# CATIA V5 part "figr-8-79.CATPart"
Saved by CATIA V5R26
Part number: Part1
Bounding box of the stored display mesh (mm): x -35 to 35, y -116.369 to 116.369, z 0 to 117.647
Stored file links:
  D:\_Deepak\CATIA\CATIA V5-6R2016_Deepak\Resources\Part files\Partfiles\c08_catia_v5_6r2016_prt\figr-8-79.CATPart
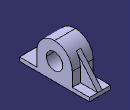
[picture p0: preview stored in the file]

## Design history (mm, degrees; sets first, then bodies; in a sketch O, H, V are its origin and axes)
Body1 (main body)
  Sketch1 on yz-plane, origin (0, 0, 0), H (0, 1, 0), V (0, 0, 1)
    line L1 (0, 0) -> (116.3687, 0)
    point P1 (116.3687, 0)
    line L2 (116.3687, 0) -> (116.3687, 12.5279)
    point P2 (116.3687, 12.5279)
    line L3 (116.3687, 12.5279) -> (58.943, 12.5279)
    point P3 (58.943, 12.5279)
    line L4 (58.943, 12.5279) -> (58.943, 58.7038)
    point P4 (58.943, 58.7038)
    arc A1 centre (0, 58.7038) radius 58.943 from (58.943, 58.7038) to (0, 117.6467) ccw
    point P5 (0, 58.7038)
    point P6 (-58.943, 58.7038)
    line L5 (-58.943, 58.7038) -> (-58.943, 12.5279)
    point P7 (-58.943, 12.5279)
    axis line L6 (0, 0) -> (0, 108.1111)
    point P9 (0, 117.6467)
    point P10 (0, 117.6467)
    point P11 (-58.943, 58.7038)
    arc A2 centre (0, 58.7038) radius 58.943 from (-58.943, 58.7038) to (0, 117.6467) cw
    point P13 (-58.943, 12.5279)
    point P14 (-116.3687, 12.5279)
    line L7 (-116.3687, 12.5279) -> (-58.943, 12.5279)
    point P15 (-116.3687, 0)
    line L8 (-116.3687, 0) -> (-116.3687, 12.5279)
    point P16 (0, 0)
    line L9 (0, 0) -> (-116.3687, 0)
    circle A3 centre (0, 58.7038) radius 27.1825
    horizontal: L1 H, L3 H
    vertical: L2 V, L4 V, L6 V
    tangency: A1 L4, L5 A1
    coincidence: P7 L3, P5 V, L6 P9, P6 P11, O P16, P9 P10, P7 P13
    symmetry: P9 P10 L6, P4 P11 L6, A1 A2 L6, P3 P13 L6, P2 P14 L6, L3 L7 L6, P1 P15 L6, L2 L8 L6, O P16 L6, L1 L9 L6
  Pad1: profile Sketch1, direction (1, 0, 0), length 35, mirrored extent
  Sketch2 on yz-plane, origin (0, 0, 0), H (0, 1, 0), V (0, 0, 1)
    line L1 (116.3687, 12.5279) -> (44.9741, 96.8037)
    point P1 (116.3687, 12.5279)
    point P2 (44.9741, 96.8037)
    reference projected arc E1 centre (0, 58.7038) radius 58.943 from (58.943, 58.7038) to (0, 117.6467) ccw from edge [face of Pad1 | face of Pad1]
    reference projected arc E2 centre (0, 58.7038) radius 58.943 from (58.943, 58.7038) to (0, 117.6467) ccw from edge [face of Pad1 | face of Pad1]
    reference projected point E3 (116.3687, 12.5279) from vertex [face of Pad1 | face of Pad1 | face of Pad1]
    tangency: L1 E1
    coincidence: P2 E2, P1 E3
  Stiffener1: ExtendedProfile Sketch2, ThicknessTop 0, ThicknessValue 15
